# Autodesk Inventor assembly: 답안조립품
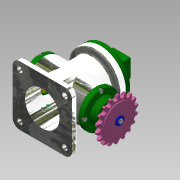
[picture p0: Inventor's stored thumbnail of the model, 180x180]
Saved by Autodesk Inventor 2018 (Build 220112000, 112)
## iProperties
Created: 2021-03
Part Number: 답안조립품
Material: 일반
Document SubType Name: Assembly
Designer: home
Author: home
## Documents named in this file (18)
- C:\Users\home\Desktop\710306V1025\답안조립품.iam
- C:\Users\home\Desktop\710306V1025\본체.ipt
- C:\Users\home\Desktop\710306V1025\베어링 17 x 40 x 12.ipt
- C:\Users\home\Desktop\710306V1025\뒤커버.ipt
- C:\Users\home\Desktop\710306V1025\편심축.ipt
- C:\Users\home\Desktop\710306V1025\앞커버.ipt
- C:\Users\home\Desktop\710306V1025\오일 실 17 30 8.ipt
- C:\Users\home\Desktop\710306V1025\스프로킷.ipt
- C:\Users\home\Desktop\710306V1025\키 4 x 4 x 12.ipt
- C:\Users\home\Desktop\710306V1025\와셔 4x16.ipt
- C:\Users\home\Desktop\710306V1025\볼트 M4 x 8.ipt
- C:\Users\home\Desktop\710306V1025\멈춤나사 M3.ipt
- C:\Users\home\Desktop\710306V1025\링크.ipt
- C:\Users\home\Desktop\710306V1025\슬라이더.ipt
- C:\Users\home\Desktop\710306V1025\클레비스 핀 6 x 22.ipt
- 클레비스 핀 6 x 22.ipt
- C:\Users\home\Desktop\710306V1025\덮개.ipt
- C:\Users\home\Desktop\710306V1025\볼트 M4 x 10.ipt
